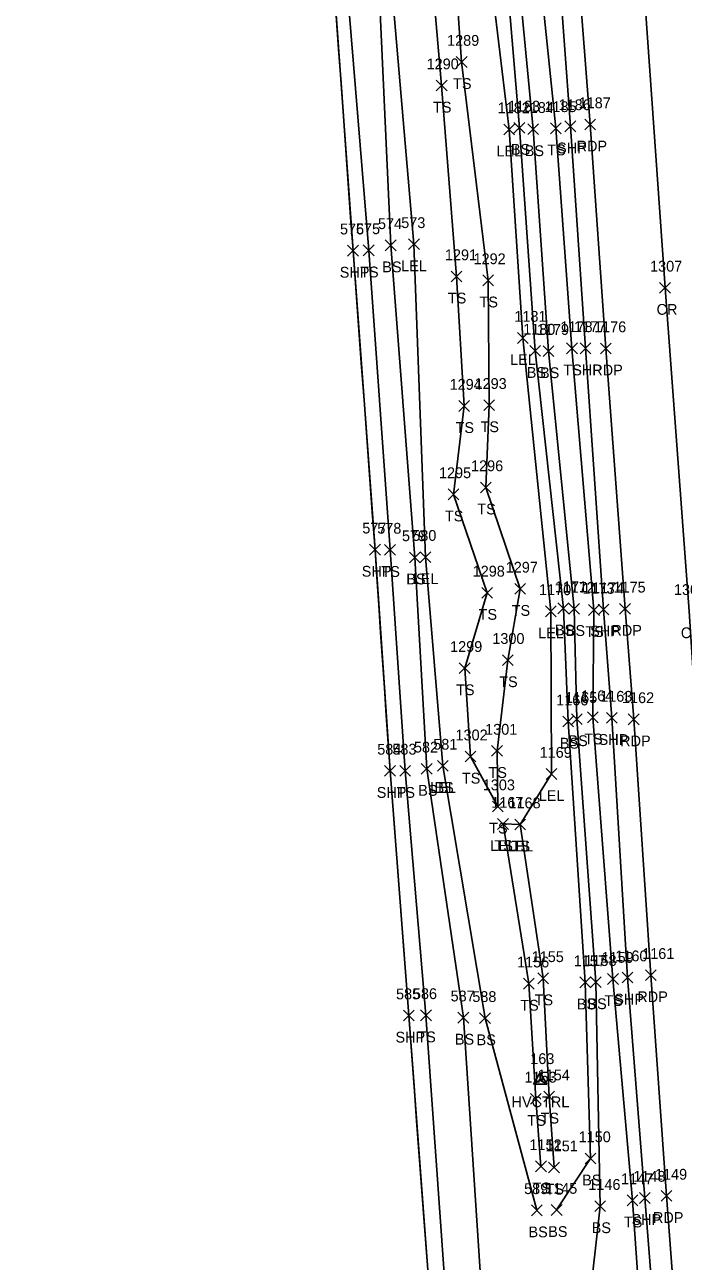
# Model space of a CAD drawing. Extents: x 1650221 to 1650634, y 244606 to 249996.
# Drawn here: x 1650231.8 to 1650353.8, y 246248.6 to 246477.6 of the extents above; entities that cross this region are included whole.
import ezdxf

# ---------------------------------------------------------------- set-up
doc = ezdxf.new("R2010")
doc.units = 0
for name, color, linetype in [('C_A', 7, 'Continuous'), ('C_I', 7, 'Continuous'), ('CPSM', 7, 'Continuous'), ('L_A', 7, 'Continuous'), ('L_I', 7, 'Continuous'), ('L_TIC', 7, 'Continuous'), ('LARO', 7, 'Continuous'), ('LELB', 7, 'Continuous'), ('LSOGP', 7, 'Continuous'), ('P_A', 7, 'Continuous'), ('P_I', 7, 'Continuous'), ('P_TIC', 7, 'Continuous'), ('PET', 7, 'Continuous'), ('PRC', 7, 'Continuous'), ('PSP', 7, 'Continuous')]:
    doc.layers.add(name, color=color, linetype=linetype)

msp = doc.modelspace()

# ---------------------------------------------------------------- linework, layer by layer
at = {"layer": 'CPSM'}
for p, q in [((1650326.04, 246281.4), (1650327.29, 246283.57)), ((1650328.54, 246281.4), (1650327.29, 246283.57)), ((1650327.29, 246282.13), (1650327.29, 246283.57)), ((1650326.04, 246281.4), (1650327.29, 246282.13)), ((1650326.04, 246281.4), (1650328.54, 246281.4)), ((1650327.29, 246282.13), (1650327.29, 246282.13)), ((1650327.29, 246282.13), (1650328.54, 246281.4))]:
    msp.add_line(p, q, dxfattribs=at)
at = {"layer": 'L_TIC'}
for points in [[(1650311.74, 246469.67), (1650313.74, 246471.67)], [(1650313.74, 246469.67), (1650311.74, 246471.67)], [(1650308.03, 246465.31), (1650310.03, 246467.31)], [(1650310.03, 246465.31), (1650308.03, 246467.31)], [(1650320.53, 246457.18), (1650322.53, 246459.18)], [(1650322.53, 246457.18), (1650320.53, 246459.18)], [(1650322.43, 246457.49), (1650324.43, 246459.49)], [(1650324.43, 246457.49), (1650322.43, 246459.49)], [(1650324.98, 246457.24), (1650326.98, 246459.24)], [(1650326.98, 246457.24), (1650324.98, 246459.24)], [(1650329.19, 246457.39), (1650331.19, 246459.39)], [(1650331.19, 246457.39), (1650329.19, 246459.39)], [(1650294.53, 246434.79), (1650296.53, 246436.79)], [(1650296.53, 246434.79), (1650294.53, 246436.79)], [(1650298.6, 246435.73), (1650300.6, 246437.73)], [(1650300.6, 246435.73), (1650298.6, 246437.73)], [(1650302.91, 246435.92), (1650304.91, 246437.92)], [(1650304.91, 246435.92), (1650302.91, 246437.92)], [(1650310.77, 246429.96), (1650312.77, 246431.96)], [(1650312.77, 246429.96), (1650310.77, 246431.96)], [(1650316.63, 246429.23), (1650318.63, 246431.23)], [(1650318.63, 246429.23), (1650316.63, 246431.23)], [(1650323.06, 246418.57), (1650325.06, 246420.57)], [(1650325.06, 246418.57), (1650323.06, 246420.57)], [(1650325.35, 246416.18), (1650327.35, 246418.18)], [(1650327.35, 246416.18), (1650325.35, 246418.18)], [(1650327.81, 246416.14), (1650329.81, 246418.14)], [(1650329.81, 246416.14), (1650327.81, 246418.14)], [(1650332.16, 246416.65), (1650334.16, 246418.65)], [(1650334.16, 246416.65), (1650332.16, 246418.65)], [(1650312.2, 246405.98), (1650314.2, 246407.98)], [(1650314.2, 246405.98), (1650312.2, 246407.98)], [(1650316.82, 246406.13), (1650318.82, 246408.13)], [(1650318.82, 246406.13), (1650316.82, 246408.13)], [(1650316.23, 246390.9), (1650318.23, 246392.9)], [(1650318.23, 246390.9), (1650316.23, 246392.9)], [(1650310.23, 246389.61), (1650312.23, 246391.61)], [(1650312.23, 246389.61), (1650310.23, 246391.61)], [(1650298.48, 246379.33), (1650300.48, 246381.33)], [(1650300.48, 246379.33), (1650298.48, 246381.33)], [(1650303.05, 246377.94), (1650305.05, 246379.94)], [(1650305.05, 246377.94), (1650303.05, 246379.94)], [(1650305.04, 246378), (1650307.04, 246380)], [(1650307.04, 246378), (1650305.04, 246380)], [(1650322.59, 246372.12), (1650324.59, 246374.12)], [(1650324.59, 246372.12), (1650322.59, 246374.12)], [(1650316.47, 246371.39), (1650318.47, 246373.39)], [(1650318.47, 246371.39), (1650316.47, 246373.39)], [(1650328.27, 246367.96), (1650330.27, 246369.96)], [(1650330.27, 246367.96), (1650328.27, 246369.96)], [(1650330.57, 246368.5), (1650332.57, 246370.5)], [(1650332.57, 246368.5), (1650330.57, 246370.5)], [(1650332.58, 246368.4), (1650334.58, 246370.4)], [(1650334.58, 246368.4), (1650332.58, 246370.4)], [(1650336.24, 246368.2), (1650338.24, 246370.2)], [(1650338.24, 246368.2), (1650336.24, 246370.2)], [(1650320.28, 246358.92), (1650322.28, 246360.92)], [(1650322.28, 246358.92), (1650320.28, 246360.92)], [(1650312.3, 246357.43), (1650314.3, 246359.43)], [(1650314.3, 246357.43), (1650312.3, 246359.43)], [(1650331.47, 246347.54), (1650333.47, 246349.54)], [(1650333.47, 246347.54), (1650331.47, 246349.54)], [(1650333.07, 246348), (1650335.07, 246350)], [(1650335.07, 246348), (1650333.07, 246350)], [(1650336.02, 246348.32), (1650338.02, 246350.32)], [(1650338.02, 246348.32), (1650336.02, 246350.32)], [(1650313.37, 246341.06), (1650315.37, 246343.06)], [(1650315.37, 246341.06), (1650313.37, 246343.06)], [(1650318.29, 246342.11), (1650320.29, 246344.11)], [(1650320.29, 246342.11), (1650318.29, 246344.11)], [(1650301.27, 246338.43), (1650303.27, 246340.43)], [(1650303.27, 246338.43), (1650301.27, 246340.43)], [(1650305.26, 246338.81), (1650307.26, 246340.81)], [(1650307.26, 246338.81), (1650305.26, 246340.81)], [(1650308.27, 246339.34), (1650310.27, 246341.34)], [(1650310.27, 246339.34), (1650308.27, 246341.34)], [(1650308.27, 246339.34), (1650310.27, 246341.34)], [(1650310.27, 246339.34), (1650308.27, 246341.34)], [(1650328.36, 246337.84), (1650330.36, 246339.84)], [(1650330.36, 246337.84), (1650328.36, 246339.84)], [(1650318.42, 246331.82), (1650320.42, 246333.82)], [(1650320.42, 246331.82), (1650318.42, 246333.82)], [(1650318.42, 246331.82), (1650320.42, 246333.82)], [(1650320.42, 246331.82), (1650318.42, 246333.82)], [(1650319.4, 246328.58), (1650321.4, 246330.58)], [(1650321.4, 246328.58), (1650319.4, 246330.58)], [(1650319.4, 246328.58), (1650321.4, 246330.58)], [(1650321.4, 246328.58), (1650319.4, 246330.58)], [(1650322.59, 246328.49), (1650324.59, 246330.49)], [(1650324.59, 246328.49), (1650322.59, 246330.49)], [(1650322.59, 246328.49), (1650324.59, 246330.49)], [(1650324.59, 246328.49), (1650322.59, 246330.49)], [(1650324.18, 246299.02), (1650326.18, 246301.02)], [(1650326.18, 246299.02), (1650324.18, 246301.02)], [(1650326.84, 246300.01), (1650328.84, 246302.01)], [(1650328.84, 246300.01), (1650326.84, 246302.01)], [(1650334.63, 246299.25), (1650336.63, 246301.25)], [(1650336.63, 246299.25), (1650334.63, 246301.25)], [(1650336.59, 246299.3), (1650338.59, 246301.3)], [(1650338.59, 246299.3), (1650336.59, 246301.3)], [(1650339.76, 246299.88), (1650341.76, 246301.88)], [(1650341.76, 246299.88), (1650339.76, 246301.88)], [(1650305.13, 246293.16), (1650307.13, 246295.16)], [(1650307.13, 246293.16), (1650305.13, 246295.16)], [(1650312.05, 246292.73), (1650314.05, 246294.73)], [(1650314.05, 246292.73), (1650312.05, 246294.73)], [(1650316.07, 246292.62), (1650318.07, 246294.62)], [(1650318.07, 246292.62), (1650316.07, 246294.62)], [(1650327.95, 246278.12), (1650329.95, 246280.12)], [(1650329.95, 246278.12), (1650327.95, 246280.12)], [(1650325.49, 246277.7), (1650327.49, 246279.7)], [(1650327.49, 246277.7), (1650325.49, 246279.7)], [(1650335.61, 246266.66), (1650337.61, 246268.66)], [(1650337.61, 246266.66), (1650335.61, 246268.66)], [(1650326.42, 246265.19), (1650328.42, 246267.19)], [(1650328.42, 246265.19), (1650326.42, 246267.19)], [(1650328.85, 246264.97), (1650330.85, 246266.97)], [(1650330.85, 246264.97), (1650328.85, 246266.97)], [(1650337.38, 246257.83), (1650339.38, 246259.83)], [(1650339.38, 246257.83), (1650337.38, 246259.83)], [(1650343.37, 246258.89), (1650345.37, 246260.89)], [(1650345.37, 246258.89), (1650343.37, 246260.89)], [(1650325.67, 246257.05), (1650327.67, 246259.05)], [(1650327.67, 246257.05), (1650325.67, 246259.05)], [(1650329.33, 246257.11), (1650331.33, 246259.11)], [(1650331.33, 246257.11), (1650329.33, 246259.11)]]:
    msp.add_lwpolyline(points, dxfattribs=at)
at = {"layer": 'LARO'}
for points in [[(1650320.4, 246329.58), (1650323.59, 246329.49), (1650329.36, 246338.84), (1650329.27, 246368.96), (1650324.06, 246419.57), (1650321.53, 246458.18), (1650315.47, 246508.37), (1650313.59, 246554.92), (1650309.88, 246602.74), (1650309.83, 246611.06), (1650305.72, 246608.28), (1650302.28, 246606.8)], [(1650294.1, 246603.38), (1650295.38, 246586.14), (1650297.83, 246539.36), (1650299.92, 246483.05), (1650303.91, 246436.92), (1650306.04, 246379), (1650309.27, 246340.34)]]:
    msp.add_lwpolyline(points, dxfattribs=at)
at = {"layer": 'LELB'}
for points in [[(1650242.27, 247235.36), (1650241.91, 247206.66), (1650243.27, 247168.76), (1650246.51, 247128.17), (1650248.83, 247083.97), (1650252.85, 247030.65), (1650256.86, 246977.49), (1650260.95, 246918.52), (1650265.57, 246863.83), (1650269.89, 246812.16), (1650273.23, 246757.17), (1650276.03, 246723.56), (1650279.21, 246672.89), (1650281.34, 246632.54), (1650285.04, 246583.81), (1650287.41, 246538.25), (1650291.5, 246485.31), (1650295.53, 246435.79), (1650299.48, 246380.33), (1650302.27, 246339.43), (1650306.13, 246294.16), (1650309.79, 246242.03)], [(1650254.94, 247226.35), (1650251.19, 247207.91), (1650256.12, 247169.21), (1650259.77, 247133.43), (1650260.76, 247116.75), (1650264.32, 247083.63), (1650267.53, 247032.12), (1650271.47, 246976.78), (1650276.33, 246918.79), (1650279.06, 246862.8), (1650283.73, 246813.9), (1650289.01, 246756.82), (1650289.41, 246725.67), (1650289.28, 246672.86), (1650289.57, 246632.6), (1650292.55, 246585.88), (1650294.65, 246538.84), (1650297.54, 246482.61), (1650299.6, 246436.73), (1650304.05, 246378.94), (1650306.26, 246339.81), (1650313.05, 246293.73), (1650316.43, 246243)], [(1650334.26, 246221.72), (1650338.38, 246258.83), (1650337.59, 246300.3), (1650334.07, 246349), (1650333.58, 246369.4), (1650328.81, 246417.14), (1650325.98, 246458.24), (1650321.21, 246507.78), (1650319.29, 246555.26), (1650315.49, 246602.23), (1650308.36, 246659.65), (1650298.25, 246716.86), (1650297.89, 246733.14), (1650297.15, 246741.44), (1650293.34, 246760.07), (1650289.93, 246790.87)], [(1650347.02, 246221.82), (1650344.37, 246259.89), (1650340.76, 246300.88), (1650337.02, 246349.32), (1650337.24, 246369.2), (1650333.16, 246417.65), (1650330.19, 246458.39), (1650325.17, 246506.95), (1650322.34, 246555.74), (1650319.08, 246602.05), (1650314.68, 246660.27), (1650309.78, 246717), (1650303.8, 246759.84), (1650302.49, 246790.4)], [(1650330.33, 246258.11), (1650336.61, 246267.66), (1650335.63, 246300.25), (1650332.47, 246348.54), (1650331.57, 246369.5), (1650326.35, 246417.18), (1650323.43, 246458.49), (1650319.31, 246507.77), (1650317.45, 246555.33), (1650313.31, 246602.42), (1650309.77, 246630.78), (1650304.43, 246659.77), (1650299.11, 246683.43)], [(1650298.24, 246680.39), (1650300.27, 246657.56), (1650304.04, 246629.74), (1650305.72, 246608.28), (1650308.61, 246573.85), (1650309.06, 246546.86), (1650310.07, 246509.23), (1650312.74, 246470.67), (1650317.63, 246430.23), (1650317.82, 246407.13), (1650317.23, 246391.9), (1650323.59, 246373.12), (1650321.28, 246359.92), (1650319.29, 246343.11), (1650319.42, 246332.82)], [(1650298.24, 246680.39), (1650298.51, 246657.16), (1650299.98, 246629.97), (1650302.28, 246606.8), (1650303.3, 246573.46), (1650304.74, 246545.53), (1650305.21, 246510.64), (1650309.03, 246466.31), (1650311.77, 246430.96), (1650313.2, 246406.98), (1650311.23, 246390.61), (1650317.47, 246372.39), (1650313.3, 246358.43), (1650314.37, 246342.06), (1650319.42, 246332.82)], [(1650309.27, 246340.34), (1650317.07, 246293.62), (1650326.67, 246258.05)], [(1650327.42, 246266.19), (1650326.49, 246278.7), (1650325.18, 246300.02), (1650320.4, 246329.58)], [(1650329.85, 246265.97), (1650328.95, 246279.12), (1650327.84, 246301.01), (1650323.59, 246329.49)]]:
    msp.add_lwpolyline(points, dxfattribs=at)
at = {"layer": 'LSOGP'}
msp.add_lwpolyline([(1650289.51, 246479.26), (1650289.95, 246473.04), (1650290.4, 246466.83), (1650290.85, 246460.61), (1650291.29, 246454.39), (1650291.74, 246448.17), (1650292.18, 246441.96), (1650292.63, 246435.74), (1650293.14, 246428.82), (1650293.65, 246421.9), (1650294.16, 246414.97), (1650294.67, 246408.05), (1650295.18, 246401.13), (1650295.68, 246394.21), (1650296.19, 246387.29), (1650296.7, 246380.37), (1650297.05, 246375.25), (1650297.4, 246370.13), (1650297.74, 246365.01), (1650298.09, 246359.89), (1650298.44, 246354.77), (1650298.78, 246349.65), (1650299.13, 246344.54), (1650299.48, 246339.42), (1650299.91, 246333.75), (1650300.35, 246328.09), (1650300.78, 246322.43), (1650301.21, 246316.77), (1650301.65, 246311.1), (1650302.08, 246305.44), (1650302.52, 246299.78), (1650302.95, 246294.11), (1650303.44, 246287.61), (1650303.92, 246281.11), (1650304.4, 246274.61), (1650304.89, 246268.11), (1650305.37, 246261.61), (1650305.85, 246255.11), (1650306.34, 246248.61)], dxfattribs=at)
at = {"layer": 'P_TIC'}
for points in [[(1650331.87, 246457.75), (1650333.87, 246459.75)], [(1650333.87, 246457.75), (1650331.87, 246459.75)], [(1650335.53, 246458.1), (1650337.53, 246460.1)], [(1650337.53, 246458.1), (1650335.53, 246460.1)], [(1650291.63, 246434.74), (1650293.63, 246436.74)], [(1650293.63, 246434.74), (1650291.63, 246436.74)], [(1650349.4, 246427.86), (1650351.4, 246429.86)], [(1650351.4, 246427.86), (1650349.4, 246429.86)], [(1650334.68, 246416.66), (1650336.68, 246418.66)], [(1650336.68, 246416.66), (1650334.68, 246418.66)], [(1650338.44, 246416.63), (1650340.44, 246418.63)], [(1650340.44, 246416.63), (1650338.44, 246418.63)], [(1650295.7, 246379.37), (1650297.7, 246381.37)], [(1650297.7, 246379.37), (1650295.7, 246381.37)], [(1650337.99, 246368.3), (1650339.99, 246370.3)], [(1650339.99, 246368.3), (1650337.99, 246370.3)], [(1650341.99, 246368.43), (1650343.99, 246370.43)], [(1650343.99, 246368.43), (1650341.99, 246370.43)], [(1650339.56, 246348.22), (1650341.56, 246350.22)], [(1650341.56, 246348.22), (1650339.56, 246350.22)], [(1650343.6, 246347.96), (1650345.6, 246349.96)], [(1650345.6, 246347.96), (1650343.6, 246349.96)], [(1650298.48, 246338.42), (1650300.48, 246340.42)], [(1650300.48, 246338.42), (1650298.48, 246340.42)], [(1650342.46, 246300.15), (1650344.46, 246302.15)], [(1650344.46, 246300.15), (1650342.46, 246302.15)], [(1650346.78, 246300.59), (1650348.78, 246302.59)], [(1650348.78, 246300.59), (1650346.78, 246302.59)], [(1650301.95, 246293.11), (1650303.95, 246295.11)], [(1650303.95, 246293.11), (1650301.95, 246295.11)], [(1650345.67, 246259.34), (1650347.67, 246261.34)], [(1650347.67, 246259.34), (1650345.67, 246261.34)], [(1650349.67, 246259.72), (1650351.67, 246261.72)], [(1650351.67, 246259.72), (1650349.67, 246261.72)]]:
    msp.add_lwpolyline(points, dxfattribs=at)
at = {"layer": 'PET'}
msp.add_lwpolyline([(1650353.63, 246221.52), (1650350.67, 246260.72), (1650347.78, 246301.59), (1650344.6, 246348.96), (1650342.99, 246369.43), (1650339.44, 246417.63), (1650336.53, 246459.1), (1650332.81, 246507), (1650329.1, 246556.8), (1650325.84, 246602.52), (1650321.75, 246661.01), (1650317.87, 246717.27), (1650314.55, 246761.47), (1650311.27, 246802.48), (1650308.51, 246843.59), (1650304.95, 246897.23), (1650300.96, 246950.35), (1650297.4, 247001.83), (1650293.63, 247056.22), (1650290.13, 247106.77), (1650285.97, 247166.23), (1650282.75, 247212.34), (1650279.98, 247248.95)], dxfattribs=at)
at = {"layer": 'PRC'}
msp.add_lwpolyline([(1650365.1, 246222.23), (1650362.04, 246265.67), (1650358.21, 246317.53), (1650354.88, 246368.98), (1650350.4, 246428.86), (1650346.57, 246483.13), (1650341.97, 246537.02), (1650338.57, 246591.04), (1650334.55, 246647.32), (1650330.72, 246698.07), (1650326.82, 246753.45), (1650322.93, 246808.73), (1650318.78, 246866.3), (1650315.63, 246915.25), (1650311.69, 246971.18), (1650308.09, 247021.19), (1650305.21, 247068.94), (1650301.6, 247120.36), (1650298.8, 247160.8), (1650294.82, 247207.2), (1650291.45, 247257.79)], dxfattribs=at)
at = {"layer": 'PSP'}
for points in [[(1650231.83, 247264.44), (1650236.38, 247206.75), (1650239.4, 247169.19), (1650242.51, 247127.54), (1650245.5, 247084.02), (1650249.81, 247030.22), (1650253.62, 246978.01), (1650257.98, 246918.58), (1650261.69, 246863.47), (1650265.43, 246811.71), (1650269.36, 246757.46), (1650271.77, 246723.3), (1650275.43, 246673.04), (1650278.75, 246632.2), (1650282.06, 246584.21), (1650285.45, 246538.51), (1650289.06, 246485.48), (1650292.63, 246435.74), (1650296.7, 246380.37), (1650299.48, 246339.42), (1650302.95, 246294.11), (1650306.82, 246242.11)], [(1650349.68, 246222.04), (1650346.67, 246260.34), (1650343.46, 246301.15), (1650340.56, 246349.22), (1650338.99, 246369.3), (1650335.68, 246417.66), (1650332.87, 246458.75), (1650329.36, 246506.58), (1650325.51, 246556.6), (1650322.14, 246602.26), (1650317.67, 246660.67), (1650313.65, 246716.62), (1650310.76, 246760.87), (1650307.66, 246803.03), (1650304.71, 246843.75), (1650300.95, 246897.67), (1650297.16, 246949.75), (1650293.72, 247001.93), (1650289.97, 247055.55), (1650286.03, 247107.65), (1650281.83, 247165.68), (1650278.51, 247212.85), (1650276.66, 247249.86)]]:
    msp.add_lwpolyline(points, dxfattribs=at)

# ---------------------------------------------------------------- texts
at = {"layer": 'C_A'}
msp.add_text('HVCTRL', height=2, dxfattribs=at).set_placement((1650321.98, 246277.13))
at = {"layer": 'C_I'}
msp.add_text('163', height=2, dxfattribs=at).set_placement((1650325.44, 246285.13))
at = {"layer": 'L_A'}
for s, p in [('TS', (1650311.15, 246465.67)), ('TS', (1650307.44, 246461.31)), ('LEL', (1650319.17, 246453.18)), ('BS', (1650321.87, 246453.49)), ('BS', (1650324.42, 246453.24)), ('TS', (1650328.6, 246453.39)), ('BS', (1650298.04, 246431.73)), ('LEL', (1650301.55, 246431.92)), ('TS', (1650293.94, 246430.79)), ('TS', (1650310.18, 246425.96)), ('TS', (1650316.04, 246425.23)), ('LEL', (1650321.69, 246414.57)), ('BS', (1650324.79, 246412.18)), ('BS', (1650327.25, 246412.14)), ('TS', (1650331.57, 246412.65)), ('TS', (1650311.61, 246401.98)), ('TS', (1650316.23, 246402.13)), ('TS', (1650315.64, 246386.9)), ('TS', (1650309.64, 246385.61)), ('TS', (1650297.89, 246375.33)), ('BS', (1650302.49, 246373.94)), ('LEL', (1650303.68, 246374)), ('TS', (1650315.88, 246367.39)), ('TS', (1650322, 246368.12)), ('LEL', (1650326.91, 246363.96)), ('BS', (1650330.01, 246364.5)), ('BS', (1650332.02, 246364.4)), ('TS', (1650335.65, 246364.2)), ('TS', (1650319.69, 246354.92)), ('TS', (1650311.71, 246353.43)), ('BS', (1650330.91, 246343.54)), ('BS', (1650332.52, 246344)), ('TS', (1650335.43, 246344.32)), ('TS', (1650317.7, 246338.11)), ('LEL', (1650306.91, 246335.34)), ('BS', (1650307.71, 246335.34)), ('TS', (1650312.78, 246337.06)), ('TS', (1650300.68, 246334.43)), ('BS', (1650304.7, 246334.81)), ('LEL', (1650327, 246333.84)), ('TS', (1650317.83, 246327.82)), ('TS', (1650317.83, 246327.82)), ('LEL', (1650318.04, 246324.58)), ('TS', (1650318.81, 246324.58)), ('LEL', (1650321.23, 246324.49)), ('TS', (1650322, 246324.49)), ('TS', (1650323.59, 246295.02)), ('TS', (1650326.25, 246296.01)), ('BS', (1650334.07, 246295.25)), ('BS', (1650336.03, 246295.3)), ('TS', (1650339.17, 246295.88)), ('TS', (1650304.54, 246289.16)), ('BS', (1650311.49, 246288.73)), ('BS', (1650315.51, 246288.62)), ('TS', (1650324.9, 246273.7)), ('TS', (1650327.36, 246274.12)), ('BS', (1650335.05, 246262.66)), ('TS', (1650325.83, 246261.19)), ('TS', (1650328.26, 246260.97)), ('BS', (1650325.11, 246253.05)), ('BS', (1650328.77, 246253.11)), ('BS', (1650336.82, 246253.83)), ('TS', (1650342.78, 246254.89))]:
    msp.add_text(s, height=2, dxfattribs=at).set_placement(p)
at = {"layer": 'L_I'}
for s, p in [('1289', (1650310.04, 246473.67)), ('1290', (1650306.25, 246469.31)), ('1183', (1650321.31, 246461.49)), ('1184', (1650323.86, 246461.24)), ('1185', (1650328.07, 246461.39)), ('1182', (1650319.41, 246461.18)), ('575', (1650293.17, 246438.79)), ('574', (1650297.24, 246439.73)), ('573', (1650301.55, 246439.92)), ('1291', (1650309.64, 246433.96)), ('1292', (1650314.94, 246433.23)), ('1181', (1650322.5, 246422.57)), ('1180', (1650324.14, 246420.18)), ('1179', (1650326.67, 246420.14)), ('1178', (1650331.03, 246420.65)), ('1294', (1650310.51, 246409.98)), ('1293', (1650315.13, 246410.13)), ('1296', (1650314.48, 246394.9)), ('1295', (1650308.54, 246393.61)), ('578', (1650297.11, 246383.33)), ('579', (1650301.68, 246381.94)), ('580', (1650303.59, 246382)), ('1298', (1650314.78, 246375.39)), ('1297', (1650320.9, 246376.12)), ('1170', (1650327.06, 246371.96)), ('1171', (1650330.01, 246372.5)), ('1172', (1650331.45, 246372.4)), ('1173', (1650335.11, 246372.2)), ('1300', (1650318.42, 246362.92)), ('1299', (1650310.6, 246361.43)), ('1166', (1650330.24, 246351.54)), ('1165', (1650331.9, 246352)), ('1164', (1650334.85, 246352.32)), ('1302', (1650311.6, 246345.06)), ('1301', (1650317.09, 246346.11)), ('583', (1650299.91, 246342.43)), ('582', (1650303.9, 246342.81)), ('581', (1650307.48, 246343.34)), ('581', (1650307.48, 246343.34)), ('1169', (1650327.18, 246341.84)), ('1303', (1650316.65, 246335.82)), ('1303', (1650316.65, 246335.82)), ('1167', (1650318.23, 246332.58)), ('1167', (1650318.23, 246332.58)), ('1168', (1650321.41, 246332.49)), ('1168', (1650321.41, 246332.49)), ('1155', (1650325.71, 246304.01)), ('1158', (1650335.47, 246303.3)), ('1159', (1650338.63, 246303.88)), ('1156', (1650323, 246303.02)), ('1157', (1650333.5, 246303.25)), ('586', (1650303.71, 246297.16)), ('587', (1650310.69, 246296.73)), ('588', (1650314.71, 246296.62)), ('1153', (1650324.37, 246281.7)), ('1154', (1650326.82, 246282.12)), ('1152', (1650325.29, 246269.19)), ('1151', (1650328.29, 246268.97)), ('1150', (1650334.4, 246270.66)), ('1147', (1650342.25, 246262.89)), ('589', (1650324.3, 246261.05)), ('1145', (1650328.2, 246261.11)), ('1146', (1650336.2, 246261.83))]:
    msp.add_text(s, height=2, dxfattribs=at).set_placement(p)
at = {"layer": 'P_A'}
for s, p in [('SHP', (1650330.41, 246453.75)), ('RDP', (1650334.02, 246454.1)), ('SHP', (1650290.16, 246430.74)), ('CR', (1650348.83, 246423.86)), ('SHP', (1650333.22, 246412.66)), ('RDP', (1650336.93, 246412.63)), ('SHP', (1650294.24, 246375.37)), ('SHP', (1650336.53, 246364.3)), ('RDP', (1650340.47, 246364.43)), ('CR', (1650353.32, 246363.98)), ('SHP', (1650338.1, 246344.22)), ('RDP', (1650342.09, 246343.96)), ('SHP', (1650297.01, 246334.42)), ('RDP', (1650345.27, 246296.59)), ('SHP', (1650341, 246296.15)), ('SHP', (1650300.49, 246289.11)), ('SHP', (1650344.2, 246255.34)), ('RDP', (1650348.16, 246255.72))]:
    msp.add_text(s, height=2, dxfattribs=at).set_placement(p)
at = {"layer": 'P_I'}
for s, p in [('1186', (1650330.69, 246461.75)), ('1187', (1650334.4, 246462.1)), ('576', (1650290.21, 246438.74)), ('1307', (1650347.63, 246431.86)), ('1177', (1650333.55, 246420.66)), ('1176', (1650337.26, 246420.63)), ('577', (1650294.34, 246383.37)), ('1174', (1650336.87, 246372.3)), ('1175', (1650340.86, 246372.43)), ('1306', (1650352.06, 246371.98)), ('1163', (1650338.39, 246352.22)), ('1162', (1650342.43, 246351.96)), ('584', (1650297.11, 246342.42)), ('1160', (1650341.2, 246304.15)), ('1161', (1650346.17, 246304.59)), ('585', (1650300.59, 246297.11)), ('1148', (1650344.54, 246263.34)), ('1149', (1650348.54, 246263.72))]:
    msp.add_text(s, height=2, dxfattribs=at).set_placement(p)

doc.saveas('drawing.dxf')
